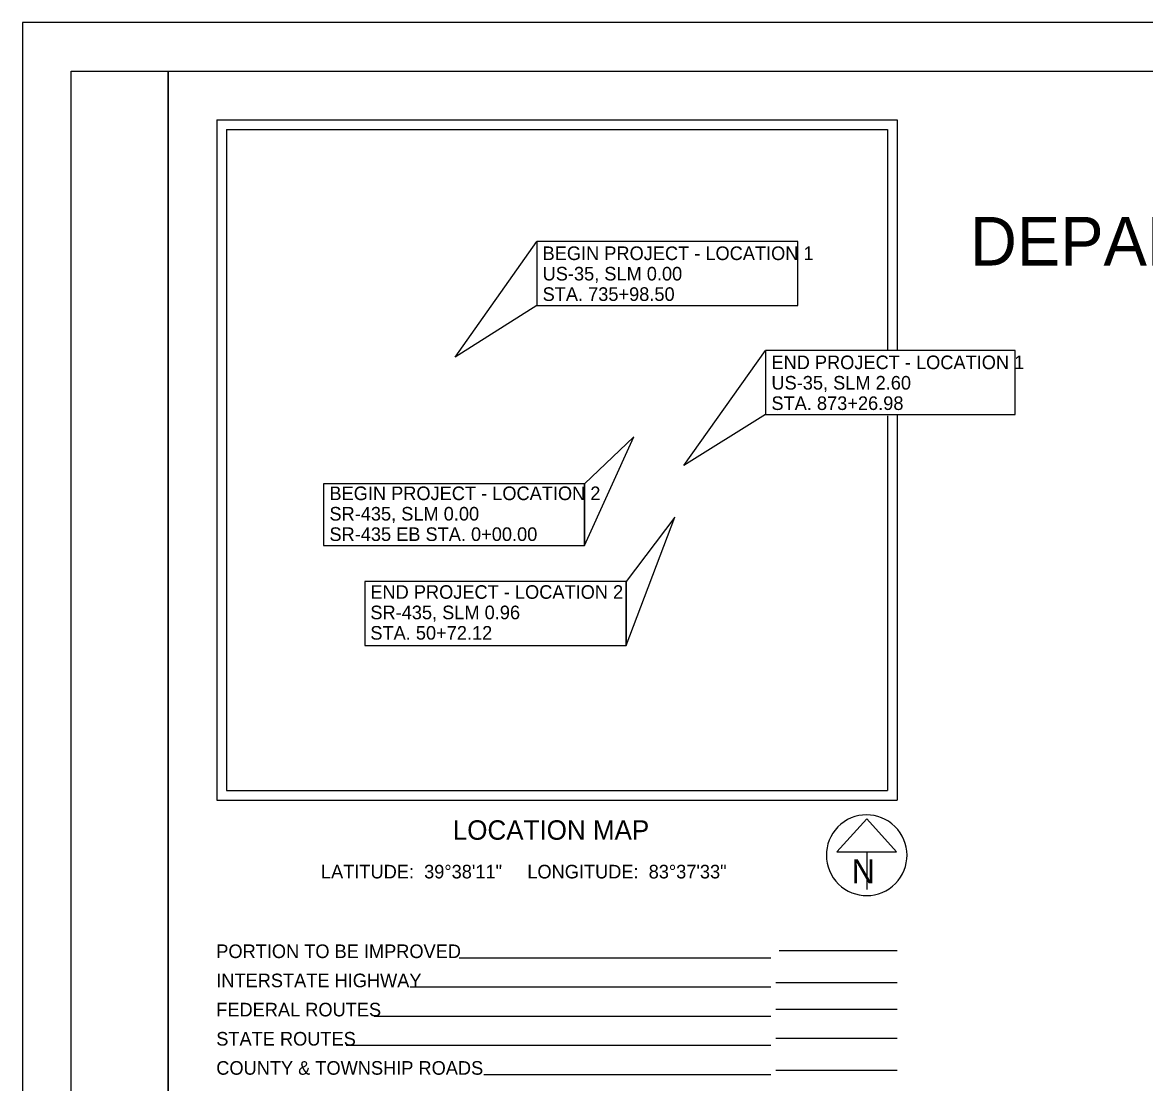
# Model space of a CAD drawing. Extents: x 0 to 34, y 0 to 22.
# Drawn here: x 0 to 11.54, y 11.1 to 22 of the extents above; entities that cross this region are included whole.
import ezdxf

# ---------------------------------------------------------------- set-up
doc = ezdxf.new("R2010")
doc.units = 0
for name, color, linetype in [('SH_Border', 7, 'Continuous'), ('SH_Cut_Line', 7, 'Continuous'), ('SH_Data', 7, 'Continuous'), ('SH_Text', 7, 'Continuous')]:
    doc.layers.add(name, color=color, linetype=linetype)

msp = doc.modelspace()

# ---------------------------------------------------------------- linework, layer by layer
at = {"layer": 'SH_Border'}
for points in [[(0.5, 21.5), (1.5, 21.5), (1.5, 0.5), (0.5, 0.5)], [(1.5, 21.5), (33.5, 21.5), (33.5, 0.5), (1.5, 0.5)]]:
    msp.add_lwpolyline(points, close=True, dxfattribs=at)
at = {"layer": 'SH_Cut_Line'}
msp.add_lwpolyline([(0, 0), (34, 0), (34, 22), (0, 22)], close=True, dxfattribs=at)
at = {"layer": 'SH_Data'}
for p, q in [((2, 21), (9, 21)), ((2, 21), (2, 14)), ((2.1, 20.9), (2.1, 14.1)), ((2.1, 20.9), (8.9, 20.9)), ((8.9, 20.9), (8.9, 18.625)), ((9, 21), (9, 18.625)), ((8.9, 17.955), (8.9, 14.1)), ((9, 17.966), (9, 14)), ((2.1, 14.1), (8.9, 14.1)), ((2.1, 14.1), (2.1, 14.1)), ((2, 14), (9, 14)), ((8.685, 13.809), (8.377, 13.468)), ((8.992, 13.468), (8.685, 13.809)), ((8.377, 13.468), (8.992, 13.468)), ((8.685, 13.468), (8.685, 13.081)), ((8.685, 13.435), (8.685, 13.435)), ((8.685, 13.435), (8.685, 13.435)), ((7.7, 12.377), (4.494, 12.377)), ((7.783, 12.455), (9, 12.455)), ((9, 12.121), (7.75, 12.121)), ((7.7, 12.077), (3.99, 12.077)), ((7.7, 11.777), (3.619, 11.777)), ((9, 11.849), (7.75, 11.849)), ((9, 11.549), (7.75, 11.549)), ((7.7, 11.477), (3.329, 11.477)), ((9, 11.222), (7.75, 11.222)), ((7.7, 11.177), (4.745, 11.177))]:
    msp.add_line(p, q, dxfattribs=at)
msp.add_arc((8.685, 13.435), 0.415, 129.7798, 129.7633, dxfattribs=at)
at = {"layer": 'SH_Text'}
for points in [[(4.45, 18.558), (5.291, 19.748), (5.291, 19.089)], [(7.976, 19.748), (5.291, 19.748), (5.291, 19.089), (7.976, 19.089)], [(6.805, 17.444), (7.645, 18.625), (7.645, 17.966)], [(10.212, 18.625), (7.645, 18.625), (7.645, 17.966), (10.212, 17.966)], [(6.29, 17.739), (5.783, 17.254), (5.783, 16.619)], [(5.783, 17.254), (3.098, 17.254), (3.098, 16.619), (5.783, 16.619)], [(6.71, 16.912), (6.209, 16.25), (6.209, 15.591)], [(6.209, 16.25), (3.523, 16.25), (3.523, 15.591), (6.209, 15.591)]]:
    msp.add_lwpolyline(points, close=True, dxfattribs=at)

# ---------------------------------------------------------------- texts
at = {"layer": 'SH_Data'}
msp.add_text('N', height=0.25, dxfattribs=at).set_placement((8.529, 13.144))
at = {"layer": 'SH_Text'}
for s, height, p in [('DEPARTMENT OF TRANSPORTATION', 0.5, (9.747, 19.5)), ('BEGIN PROJECT - LOCATION 1', 0.14, (5.351, 19.556)), ('US-35, SLM 0.00', 0.14, (5.351, 19.346)), ('STA. 735+98.50', 0.14, (5.351, 19.136)), ('END PROJECT - LOCATION 1', 0.14, (7.705, 18.434)), ('US-35, SLM 2.60', 0.14, (7.705, 18.224)), ('STA. 873+26.98', 0.14, (7.705, 18.014)), ('BEGIN PROJECT - LOCATION 2', 0.14, (3.158, 17.087)), ('SR-435, SLM 0.00', 0.14, (3.158, 16.877)), ('SR-435 EB STA. 0+00.00', 0.14, (3.158, 16.667)), ('END PROJECT - LOCATION 2', 0.14, (3.579, 16.072)), ('SR-435, SLM 0.96', 0.14, (3.579, 15.862)), ('STA. 50+72.12', 0.14, (3.579, 15.652)), ('LOCATION MAP', 0.2, (4.427, 13.594)), ('LATITUDE:  39°38\'11"     LONGITUDE:  83°37\'33"', 0.14, (3.071, 13.196)), ('PORTION TO BE IMPROVED', 0.14, (1.994, 12.377)), ('INTERSTATE HIGHWAY', 0.14, (1.994, 12.077)), ('FEDERAL ROUTES', 0.14, (1.994, 11.777)), ('STATE ROUTES', 0.14, (1.994, 11.477)), ('COUNTY & TOWNSHIP ROADS', 0.14, (1.994, 11.177))]:
    msp.add_text(s, height=height, dxfattribs=at).set_placement(p)

doc.saveas('drawing.dxf')
